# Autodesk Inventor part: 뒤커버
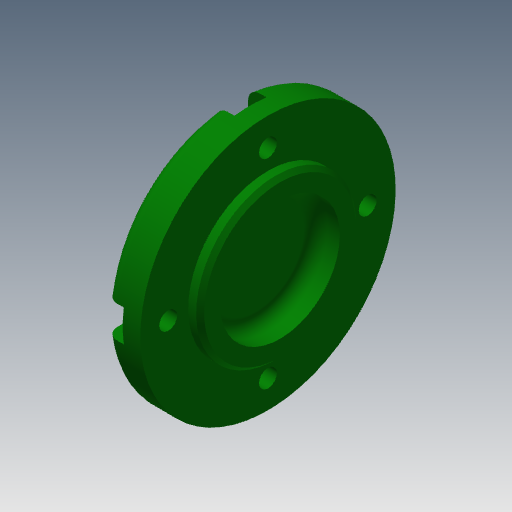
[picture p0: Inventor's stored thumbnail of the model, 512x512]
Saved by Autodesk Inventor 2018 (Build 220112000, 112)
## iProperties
Created: 2019-01
Part Number: 뒤커버
Material: 알루미늄 6061
Document SubType Name: Modeling
Designer: mduedu
Density: 2.71 g/cm^3
Appearance: 진녹색
Mass: 71.8557 g
Surface Area: 92.0216 cm^2
Volume: 26.515 cm^3
Author: mduedu
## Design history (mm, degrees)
sketch "스케치1"
  geometry: L1 (0, 0)-(9, 0); L2 (9, 0)-(9, 32); L3 (9, 32)-(0, 32); L4 (0, 32)-(0, 0); L5 (9, 0)-(12, 0); L6 (12, 0)-(12, 20); L7 (12, 20)-(9, 20); L8 (9, 20)-(9, 0)
  constraints: 16 end point, 4 parallel, 2 horizontal, 2 perpendicular
  dimensions: "d0" = 12 distance between parallel lines of L6 L4; "d2" = 64 diameter of L3 L1; "d3" = 40 diameter of L7 L5; "d4" = 3 distance between parallel lines of L6 L2
revolve "회전1" sketch "스케치1" stored, may be unused: angle "d5" = 90 deg
sketch "스케치4"
  geometry: C1 r 15 at (0, 0); 1 further point
  constraints: 1 centre point, 1 coincident
  dimensions: "d24" = 30 diameter of C1
extrude "돌출1" cut sketch "스케치4" distance "d25" = 6; taper "d26" = 0 deg
fillet "모깎기4" dims "d27" = 3
fillet "모깎기3" dims "d18" = 3
chamfer "모따기2" distance "d28" = 1; stored, may be unused: second distance "d29" = 2, angle "d30" = 45 deg
sketch "스케치3" dims "d19" = 50
  geometry: 6 further points
  constraints: 2 vertical alignment, 1 coincident, 7 other
  dimensions: "d22" = 360 deg dimension on point (0, 0) point (0, 25) (derived)
sketch "스케치5"
  geometry: 4 further points
  constraints: 4 other
hole "구멍1" sketch "스케치5" at (-25, 0), (0, -25), (25, 0), (0, 25) diameter "d31" = 4.5; stored, may be unused: countersink angle "d35" = 90 deg, drill point angle "d37" = 0 deg; dims "d32" = 6, "d33" = 8, "d34" = 4.6, "d36" = 8
sketch "스케치6"
  geometry: L1 (-4, 0)-(-4, 6.749); L2 (4, 0)-(4, 6.749); A1 r 4 centre (0, 0) between (0, 4) and (-4, 0) reference; A2 r 32 centre (0, -25) between (-4, 6.749) and (4, 6.749) reference; A3 r 4 centre (0, 0) between (-4, 0) and (4, 0); A4 r 32 centre (0, -25) between (4, 6.749) and (-4, 6.749); A5 r 4 centre (0, 0) between (4, 0) and (-4, 0); 1 further point
  constraints: 10 point on circle, 4 end point, 3 centre point, 2 coincident, 2 tangent, 1 parallel, 1 vertical
extrude "돌출2" cut sketch "스케치6" extent not by distance; stored distance "d38" = 10; taper "d39" = 0 deg
node "솔리드1"
pattern_circular "원형 패턴1" dims angle "d41" = 360 deg
